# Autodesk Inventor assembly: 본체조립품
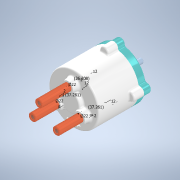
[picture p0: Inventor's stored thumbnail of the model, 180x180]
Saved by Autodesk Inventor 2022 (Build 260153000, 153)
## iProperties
Created: 2021-07
Part Number: 본체조립품
Document SubType Name: Assembly
Designer: micke
Mass: 1236.63 g
Surface Area: 1770.13 cm^2
Volume: 433.788 cm^3
Density: 2.85077 g/cm^3
Author: micke
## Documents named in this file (14)
- C:\Users\micke\Desktop\610708V1008\본체조립품.iam
- C:\Users\micke\Desktop\610708V1008\본체.ipt
- C:\Users\micke\Desktop\610708V1008\가변스프링1.ipt
- C:\Users\micke\Desktop\610708V1008\가변스프링2.ipt
- C:\Users\micke\Desktop\610708V1008\가변스프링3.ipt
- C:\Users\micke\Desktop\610708V1008\멈춤링 10 x 1.ipt
- C:\Users\micke\Desktop\610708V1008\멈춤링 22 x 1.2.ipt
- C:\Users\micke\Desktop\610708V1008\메인 축.ipt
- C:\Users\micke\Desktop\610708V1008\베어링 NA 4900.ipt
- C:\Users\micke\Desktop\610708V1008\볼트 M5.ipt
- C:\Users\micke\Desktop\610708V1008\슬라이드 축.ipt
- C:\Users\micke\Desktop\610708V1008\오일실.ipt
- C:\Users\micke\Desktop\610708V1008\커버.ipt
- C:\Users\micke\Desktop\610708V1008\판캠.ipt
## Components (3 placed, 3 different names)
1. 가변스프링1:1
2. 가변스프링2:1
3. 가변스프링3:1
